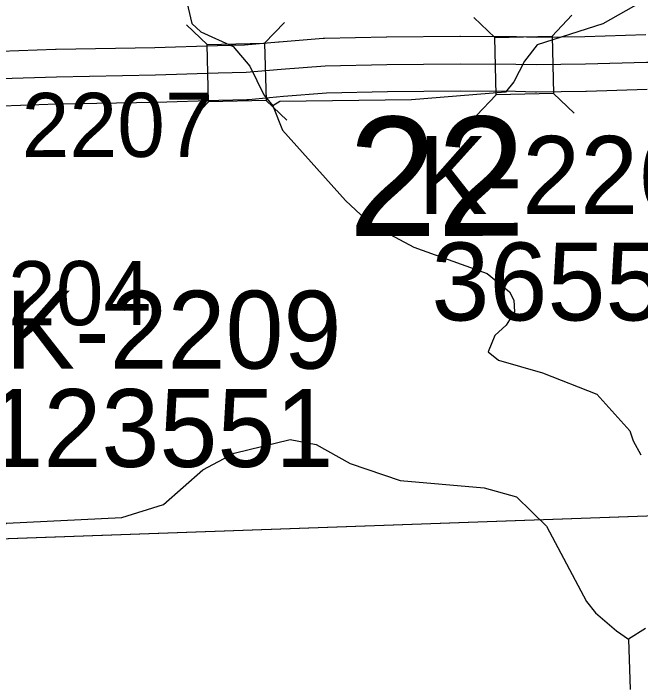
# Model space of a CAD drawing. Extents: x 128.7 to 185.5, y -21.4 to 12.6.
# Drawn here: x 149.185 to 149.869, y -5.403 to -4.672 of the extents above; entities that cross this region are included whole.
import ezdxf

# ---------------------------------------------------------------- set-up
doc = ezdxf.new("R2010")
doc.units = 0
for name, color, linetype in [('tdCoHydroRiver', 7, 'Continuous'), ('tdCoSecRdNmbr', 7, 'Continuous'), ('tdCoSecRteBand', 7, 'Continuous'), ('tdCoSecRteCL', 7, 'Continuous'), ('tdCoSectLine', 7, 'Continuous'), ('tdCoSectLinePart', 7, 'Continuous'), ('tdCoSectNmbr', 7, 'Continuous'), ('tdCoStrucSec', 7, 'Continuous'), ('tdCoStrucSecCoName', 7, 'Continuous'), ('tdCoStrucSecFHWANum', 7, 'Continuous'), ('tdCoSurfGravel', 7, 'Continuous')]:
    doc.layers.add(name, color=color, linetype=linetype)

msp = doc.modelspace()

# ---------------------------------------------------------------- linework, layer by layer
at = {"layer": 'tdCoHydroRiver'}
for points in [[(150.63402, -4.3035), (150.50269, -4.33957), (150.44833, -4.36511), (150.40347, -4.3919), (150.30682, -4.47256), (150.2555, -4.49483), (150.182, -4.51472), (150.14939, -4.53004), (150.08779, -4.57477), (150.04284, -4.59841), (149.92238, -4.62938), (149.82795, -4.68312), (149.75614, -4.70611), (149.74255, -4.72394), (149.7307, -4.74644), (149.72162, -4.75779), (149.61931, -4.76604), (149.47576, -4.76782), (149.46804, -4.77282)], [(149.37043, -4.64202), (149.37972, -4.68273), (149.3895, -4.69187), (149.42478, -4.70801), (149.44287, -4.72949), (149.45815, -4.76053), (149.46804, -4.77282), (149.47841, -4.79929), (149.54733, -4.87583), (149.57504, -4.90171), (149.62168, -4.92694), (149.70158, -4.95576), (149.72593, -4.97545), (149.73098, -4.98474), (149.73142, -4.99735), (149.72245, -5.01186), (149.71021, -5.02333), (149.70293, -5.04094), (149.71428, -5.05002), (149.76212, -5.06416), (149.82131, -5.08738), (149.8574, -5.12717), (149.86093, -5.1381), (149.86935, -5.15359)], [(149.05112, -5.40896), (149.07678, -5.37493), (149.07934, -5.35748), (149.08537, -5.34939), (149.10256, -5.29829), (149.13442, -5.2609), (149.17747, -5.22785), (149.30353, -5.22195), (149.34881, -5.20777), (149.39171, -5.16999), (149.4258, -5.15147), (149.48684, -5.13674), (149.51543, -5.14208), (149.55245, -5.1629), (149.60675, -5.18155), (149.69856, -5.18945), (149.73362, -5.19929), (149.76628, -5.23131), (149.81013, -5.31345), (149.82002, -5.32574), (149.8428, -5.34547), (149.85573, -5.3545), (149.85763, -5.40968)], [(149.87427, -5.34281), (149.85573, -5.3545)]]:
    msp.add_lwpolyline(points, dxfattribs=at)
at = {"layer": 'tdCoSecRteBand'}
for points in [[(149.17097, -4.71299), (149.23121, -4.71103), (149.23142, -4.71102), (149.23164, -4.71102), (149.33944, -4.70905), (149.40728, -4.70683), (149.40741, -4.70683), (149.40754, -4.70683), (149.43713, -4.70611), (149.47437, -4.70275), (149.47457, -4.70273), (149.47477, -4.70271), (149.52285, -4.69902), (149.52367, -4.69895), (149.52449, -4.69893), (149.59182, -4.69745), (149.59201, -4.69745), (149.5922, -4.69745), (149.6721, -4.69671), (149.67236, -4.69671), (149.67262, -4.69671), (149.73329, -4.6972), (149.7335, -4.6972), (149.73371, -4.69721), (149.75537, -4.69769), (149.80835, -4.69696), (149.87469, -4.69499)], [(149.87631, -4.75497), (149.80989, -4.75694), (149.80965, -4.75695), (149.80941, -4.75695), (149.75565, -4.75769), (149.75511, -4.7577), (149.75457, -4.75769), (149.73259, -4.7572), (149.6724, -4.75671), (149.59295, -4.75744), (149.52664, -4.7589), (149.47957, -4.76252), (149.44154, -4.76596), (149.44056, -4.76605), (149.43957, -4.76607), (149.40911, -4.76681), (149.34118, -4.76902), (149.34096, -4.76903), (149.34075, -4.76903), (149.23295, -4.771), (149.17275, -4.77297)]]:
    msp.add_lwpolyline(points, dxfattribs=at)
at = {"layer": 'tdCoSecRteCL'}
msp.add_lwpolyline([(149.17177, -4.74298), (149.23219, -4.74101), (149.3402, -4.73904), (149.40826, -4.73682), (149.43884, -4.73608), (149.47707, -4.73263), (149.52515, -4.72893), (149.59248, -4.72745), (149.67238, -4.72671), (149.73304, -4.7272), (149.75524, -4.72769), (149.809, -4.72695), (149.87558, -4.72498)], dxfattribs=at)
at = {"layer": 'tdCoSectLine'}
msp.add_lwpolyline([(149.11806, -5.24686), (150.11124, -5.21166)], dxfattribs=at)
at = {"layer": 'tdCoSectLinePart'}
msp.add_lwpolyline([(149.14802, -5.2458), (150.11124, -5.21166)], dxfattribs=at)
at = {"layer": 'tdCoStrucSec'}
for p, q in [((149.71003, -4.69805), (149.68737, -4.67646)), ((149.77262, -4.69654), (149.79421, -4.67388)), ((149.39653, -4.70578), (149.37387, -4.68419)), ((149.45911, -4.70427), (149.4807, -4.68161)), ((149.77413, -4.75912), (149.79679, -4.78071)), ((149.46063, -4.76685), (149.48329, -4.78844)), ((149.71155, -4.76064), (149.68996, -4.7833)), ((149.39804, -4.76837), (149.37645, -4.79103))]:
    msp.add_line(p, q, dxfattribs=at)
for points in [[(149.71003, -4.69805), (149.77262, -4.69654), (149.77413, -4.75912), (149.71155, -4.76064)], [(149.39653, -4.70578), (149.45911, -4.70427), (149.46063, -4.76685), (149.39804, -4.76837)]]:
    msp.add_lwpolyline(points, close=True, dxfattribs=at)
at = {"layer": 'tdCoSurfGravel'}
msp.add_lwpolyline([(148.10413, -4.77971), (148.16093, -4.77751), (148.32541, -4.77184), (148.43343, -4.76789), (148.48299, -4.76592), (148.72516, -4.75729), (148.87756, -4.75088), (148.91727, -4.7494), (149.03786, -4.7457), (149.10373, -4.74436), (149.17177, -4.74298), (149.23219, -4.74101), (149.3402, -4.73904), (149.40826, -4.73682), (149.43884, -4.73608), (149.47707, -4.73263), (149.52515, -4.72893), (149.59248, -4.72745), (149.67238, -4.72671), (149.73304, -4.7272), (149.75524, -4.72769), (149.809, -4.72695), (149.87558, -4.72498), (149.88148, -4.72487)], dxfattribs=at)

# ---------------------------------------------------------------- texts
at = {"layer": 'tdCoSecRdNmbr'}
for s, rotation, p in [('2207', 0.11326, (149.19424, -4.8287)), ('2204', 0.11319, (149.12724, -5.01228))]:
    msp.add_text(s, height=0.07, rotation=rotation, dxfattribs=at).set_placement(p)
at = {"layer": 'tdCoSectNmbr'}
msp.add_text('22', height=0.13, rotation=0.11348, dxfattribs=at).set_placement((149.5504, -4.91481))
at = {"layer": 'tdCoStrucSecCoName'}
for s, p in [('K-2265', (149.6263, -4.89055)), ('K-2209', (149.17638, -5.0594))]:
    msp.add_text(s, height=0.085, dxfattribs=at).set_placement(p)
at = {"layer": 'tdCoStrucSecFHWANum'}
for s, p in [('365530', (149.641, -5.00684)), ('123551', (149.1547, -5.16671))]:
    msp.add_text(s, height=0.085, dxfattribs=at).set_placement(p)

doc.saveas('drawing.dxf')
